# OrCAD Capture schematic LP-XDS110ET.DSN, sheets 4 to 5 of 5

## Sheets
4 4_EnergyTrace Power: size A3
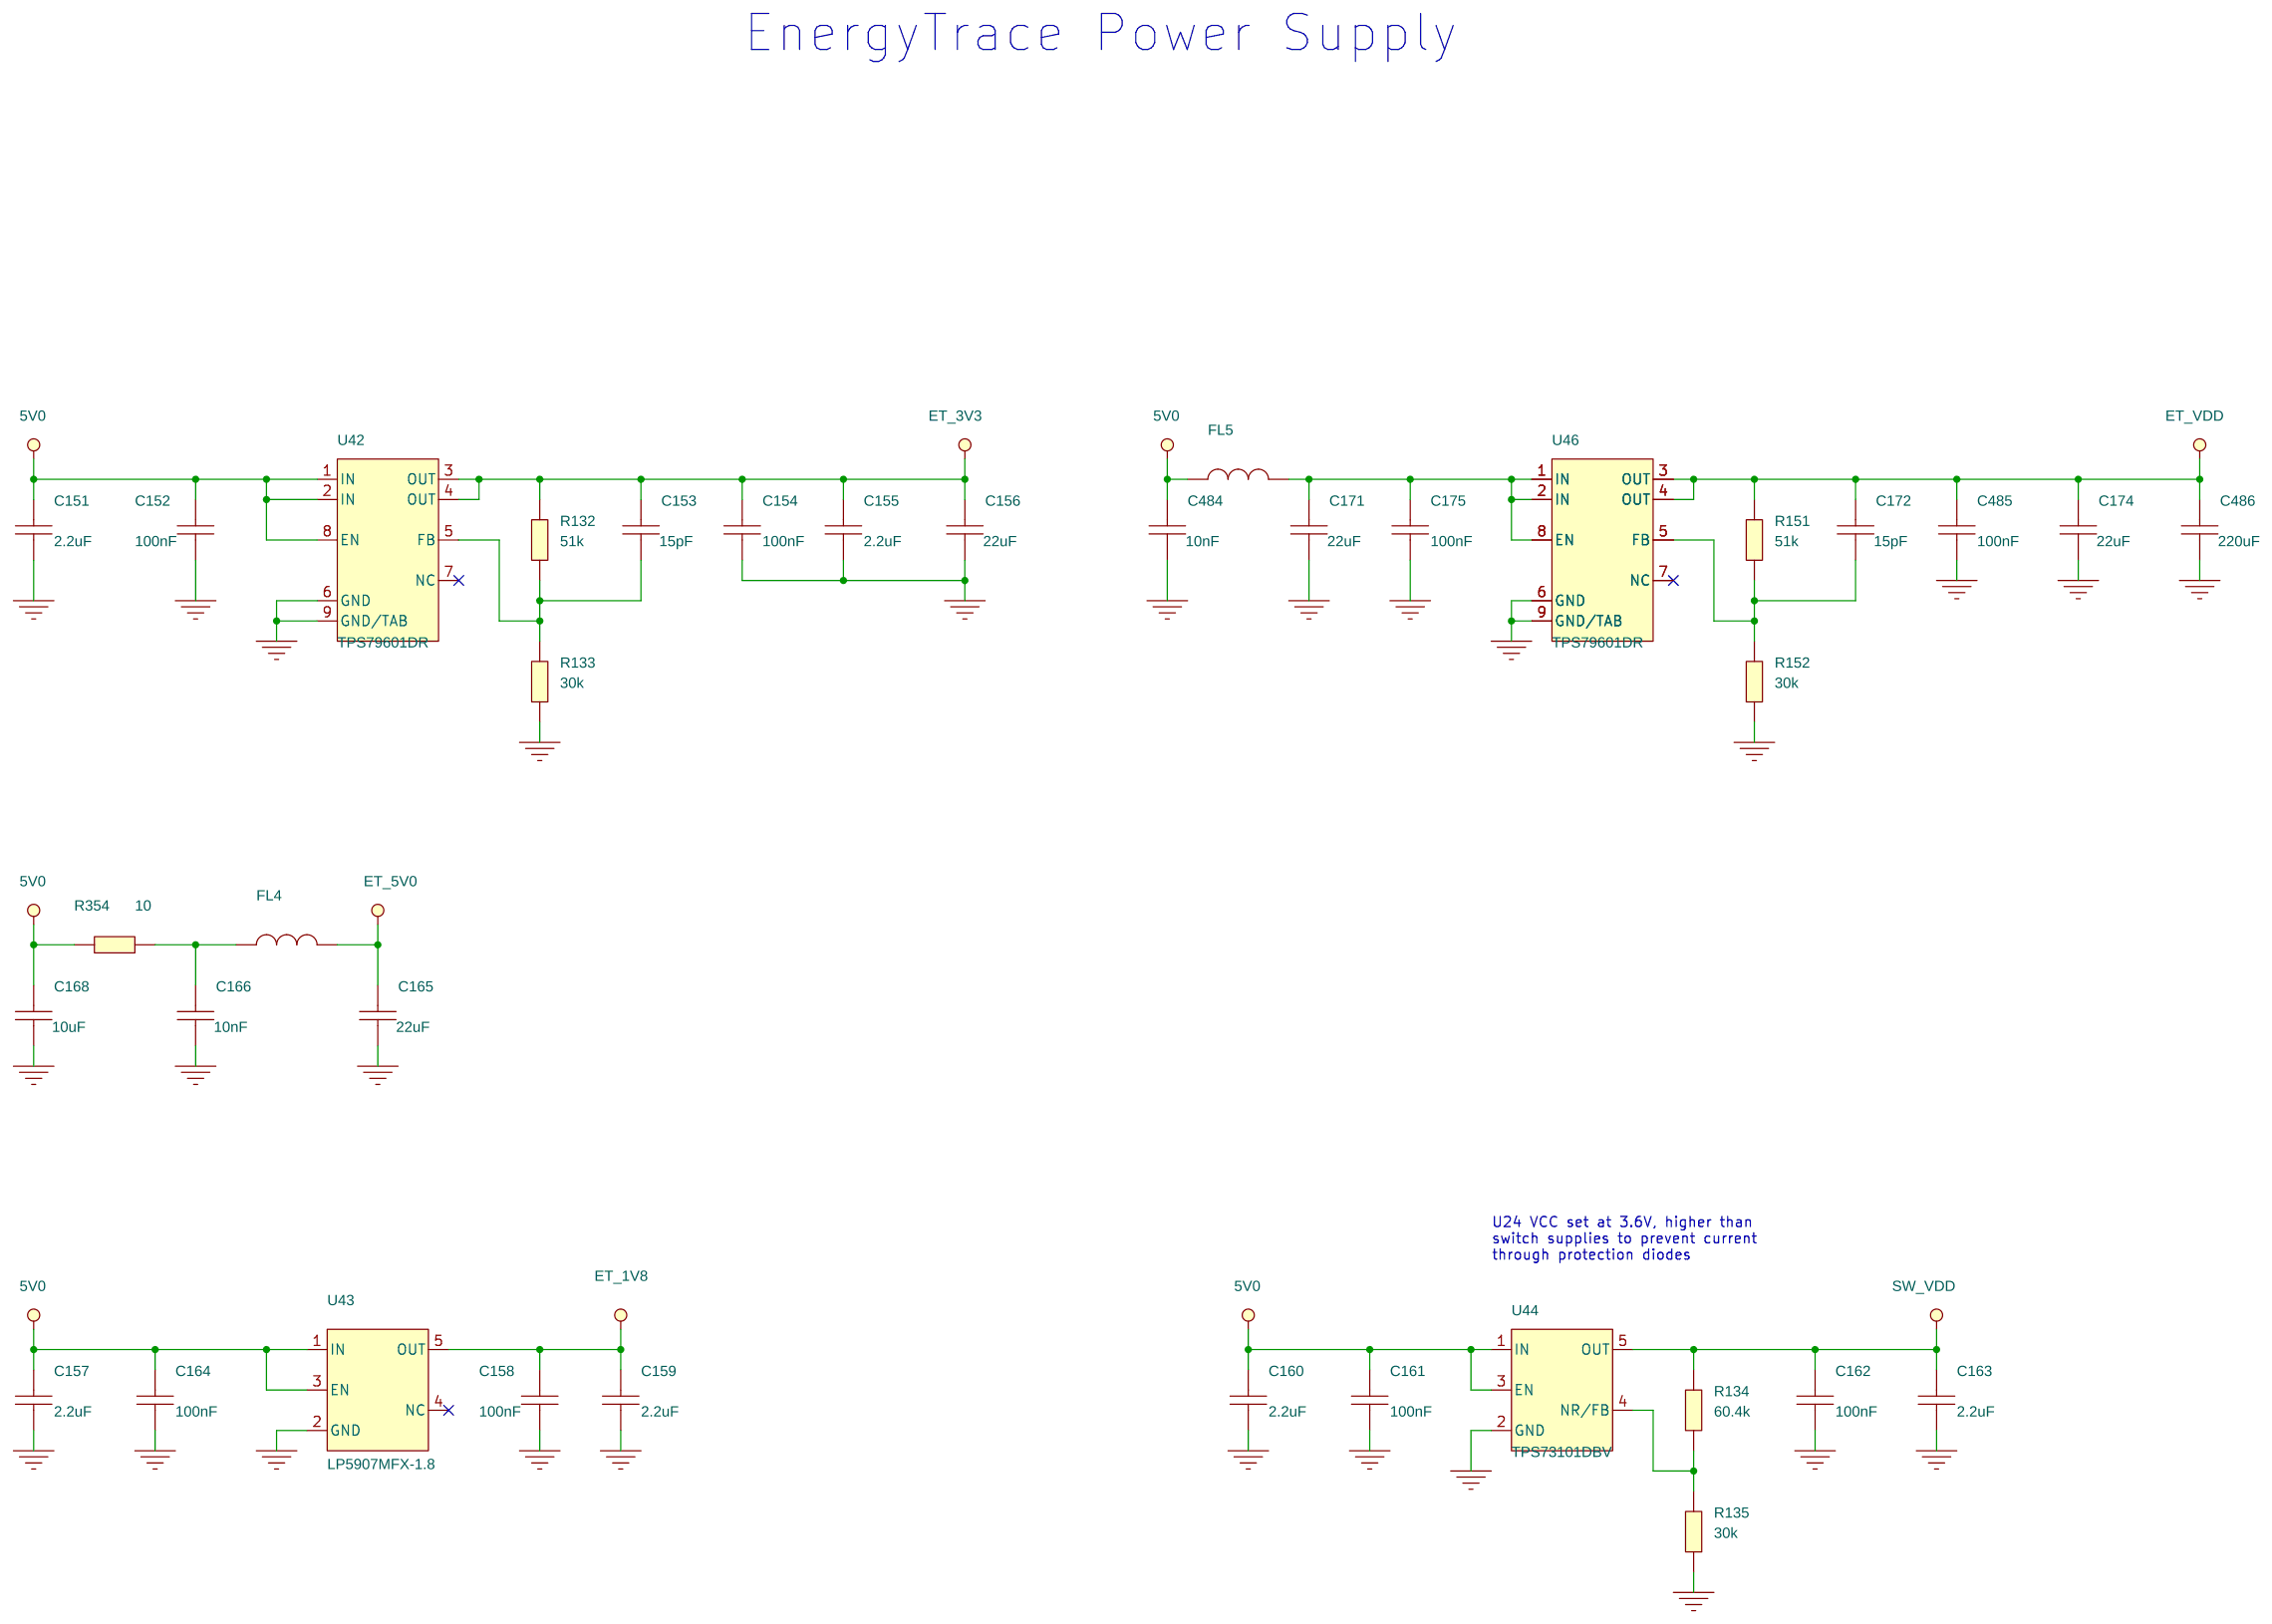
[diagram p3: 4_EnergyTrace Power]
5 5_Mech: size A3
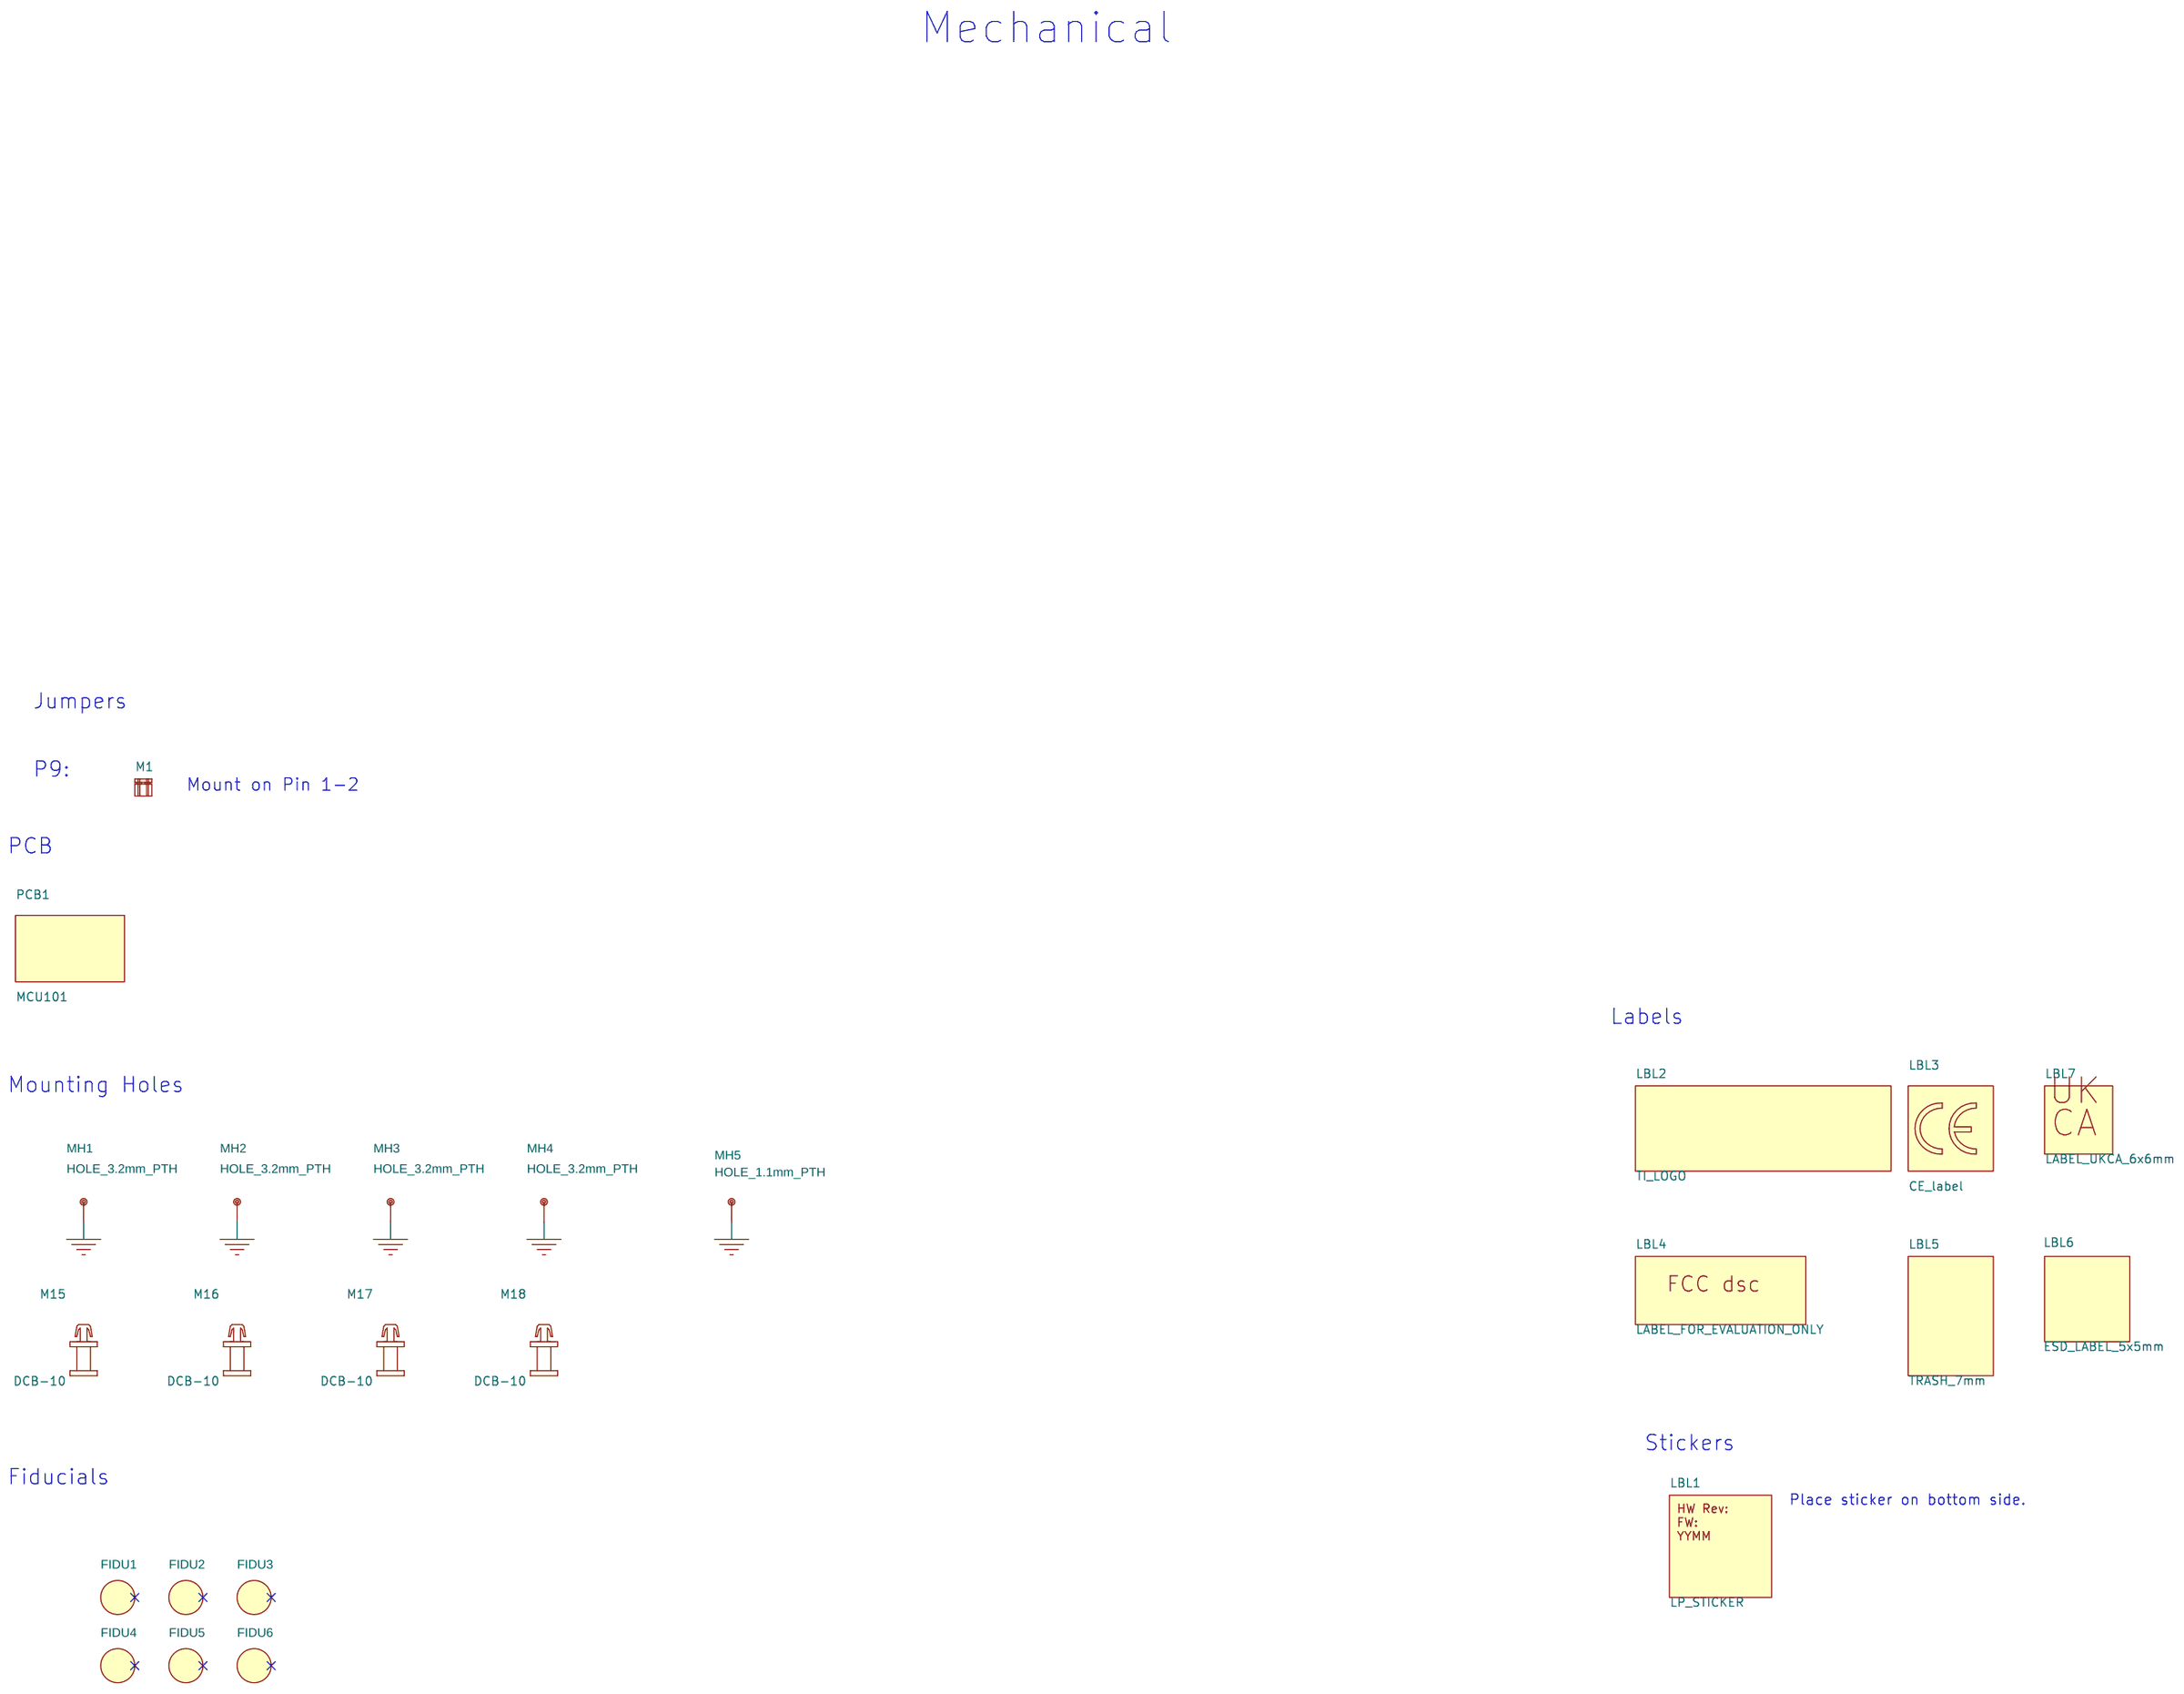
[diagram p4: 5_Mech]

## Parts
sheet 4_EnergyTrace Power
C151  2.2uF  [CAPC1005X60A2N]
C152  100nF  [CAPC0603X35B2N]
C153  15pF  [CAPC1005X60B2N]
C154  100nF  [CAPC0603X35B2N]
C155  2.2uF  [CAPC1005X60A2N]
C156  22uF  [CAPC1608X100A2N]
C157  2.2uF  [CAPC1005X60A2N]
C158  100nF  [CAPC0603X35B2N]
C159  2.2uF  [CAPC1005X60A2N]
C160  2.2uF  [CAPC1005X60A2N]
C161  100nF  [CAPC0603X35B2N]
C162  100nF  [CAPC0603X35B2N]
C163  2.2uF  [CAPC1005X60A2N]
C164  100nF  [CAPC0603X35B2N]
C165  22uF  [CAPC1608X100A2N]
C166  10nF  [CAPC1005X60B2N]
C168  10uF  [CAPC2012X150A2N]
C171  22uF  [CAPC1608X100A2N]
C172  15pF  [CAPC1005X60B2N]
C174  22uF  [CAPC1608X100A2N]
C175  100nF  [CAPC0603X35B2N]
C484  10nF  [CAPC1005X60B2N]
C485  100nF  [CAPC0603X35B2N]
C486  220uF  [CAPC3225X280A2N]
FL4  BLM18HE152SN1  [FIL_BLM18HE152SN1DN]
FL5  BLM18HE152SN1  [FIL_BLM18HE152SN1DN]
R132  51k  [RESC1005X40B2N]
R133  30k  [RESC1005X40B2N]
R134  60.4k  [RESC1005X40A2N]
R135  30k  [RESC1005X40B2N]
R151  51k  [RESC1005X40B2N]
R152  30k  [RESC1005X40B2N]
R354  10  [RESC1005X40A2N]
U42  TPS79601DR  [SON65P300X300X100-9AN]
U43  LP5907MFX-1.8  [SOT95P280X145-5A2N]
U44  TPS73101DBV  [SOT95P280X145-5A2N]
U46  TPS79601DR  [SON65P300X300X100-9AN]
sheet 5_Mech
FIDU1  FIDU_1.27mm  [FID127X142]
FIDU2  FIDU_1.27mm  [FID127X142]
FIDU3  FIDU_1.27mm  [FID127X142]
FIDU4  FIDU_1.27mm  [FID127X142]
FIDU5  FIDU_1.27mm  [FID127X142]
FIDU6  FIDU_1.27mm  [FID127X142]
LBL1  LP_STICKER
LBL2  TI_LOGO  [TI_LOGO_1]
LBL3  CE_label  [CE_MARKING]
LBL4  LABEL_FOR_EVALUATION_ONLY  [LABEL_FOR_EVALUATION_ONLY]
LBL5  TRASH_7mm  [TRASH_7MM]
LBL6  ESD_LABEL_5x5mm  [ESD_LABEL_5x5]
LBL7  LABEL_UKCA_6x6mm  [LABEL_UKCA_6MM]
M1  SNT-100-BK-G  [SAMTEC_SNT100BKG]
M15  DCB-10  [MECH_DCB10_A2B]
M16  DCB-10  [MECH_DCB10_A2B]
M17  DCB-10  [MECH_DCB10_A2B]
M18  DCB-10  [MECH_DCB10_A2B]
MH1  HOLE_3.2mm_PTH  [MTG320_380]
MH2  HOLE_3.2mm_PTH  [MTG320_380]
MH3  HOLE_3.2mm_PTH  [MTG320_380]
MH4  HOLE_3.2mm_PTH  [MTG320_380]
MH5  HOLE_1.1mm_PTH  [MTG110_170]
PCB1  MCU101  [TI_MCUxx]

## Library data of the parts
C151 C155 C157 C159 C160 C163 = CAPACITOR: CAPACITOR, CERAMIC X5R, 2.2uF, 25V, -10%/+10%, -55DEGC/+85DEGC, 0402, SMD; ALT_SYMBOLS: CAPC1005X60A2L,CAPC1005X60A2M; Additional Datasheet URL: http://search.murata.co.jp/Ceramy/image/img/w_hinm/L0005E.pdf; AutoDoc File: https://notefied-dynamic-precision.com/DB/Apps/Desktop/Item/Object.aspx?id=96297; BU Name: DYNAMIC PRECISION GDANSK; Budget Currency: EUR; Budget Price: 0.063; Budgetary Price: 0.063 EUR; Client Status: UNDER_REVIEW; Country of Origin: Missing Info; Datasheet URL: http://psearch.murata.com/capacitor/product/GRM155R61E225KE11%23.pdf; Datasheet URL 1: http://psearch.murata.com/capacitor/product/GRM155R61E225KE11%23.pdf; Datasheet URL 2: http://search.murata.co.jp/Ceramy/image/img/w_hinm/L0005E.pdf; Definied Quality: INDUSTRIAL; Dielectric Type: X5R; Esd Level: N/A; Lead Time: 19; LifeCycle Status: NRND; MPN: GRM155R60J225KE95D; MPN Status: NRND; MSL: 1; MTBF: N/A; MTBF Standard: N/A; Manufacturer: MURATA; Mass: 0.0031g; Max Oper Temp: +85DEGC; Max Tol: +10%; Maximum Operating Temperature: +85DEGC; Maximum Tolerance: +10%; Min Oper Temp: -55DEGC; Min Tol: -10%; Minimum Operating Temperature: -55DEGC; Minimum Tolerance: -10%; Mounting Type: SMD; NOTE Status: PREFERRED; NOTEfied URL: https://notefied-dynamic-precision.com/NOTEfiedWebInterface/part/show?partNumber=02-06058; Old Footprint: CAPC1005X60N; PCB Package: 0402; Packing Size: 10000; Packing Type: Tape & Reel; Part Number: 02-06058; Part Type: Capacitor|CERAMIC|0402|STANDARD; REACH/SVHC Compliance: Compliant; REACH/SVHC Details: SVHC List Version Jul 7, 2017; REACH/SVHC Source: REACH Declaration; REACH/SVHC Status: Unaffected; REACH/SVHC_COMPLIANCE: COMPLIANT; REACH/SVHC_DETAILS: SVHC List Version Jun 20, 2016; REACH/SVHC_SOURCE: REACH DECLARATION; REACH/SVHC_STATUS: UNAFFECTED; ROHS: Compliant; Rated Voltage: 25V; Revision: R007; RoHS Status: ROHS_COMPLIANT; Rtd Voltage: 25V; Status: Released; Texas Part Status: Under Review; Type: Capacitor; Vendor: MURATA; Vendor Part Number: GRM155R61E225KE11D; Vendor Part Status: Active; WEIGHT: 0.0031g
C152 C154 C158 C161 C162 C164 C175 C485 = CAPACITOR: CAPACITOR, CERAMIC X5R, 100nF, 10V, -10%/+10%, -55DEGC/+85DEGC, 0201, SMD; ALT_SYMBOLS: CAPC0603X35B2L,CAPC0603X35B2M; Additional Datasheet URL: http://psearch.en.murata.com/capacitor/product/GRM033R61A104KE84%23.html; AutoDoc File: https://notefied-dynamic-precision.com/DB/Apps/Desktop/Item/Object.aspx?id=96679; BU Name: DYNAMIC PRECISION GDANSK; Budget Currency: EUR; Budget Price: 0.008; Budgetary Price: 0.008 EUR; Client Status: UNDER_REVIEW; Country of Origin: Missing Info; Datasheet URL: http://psearch.murata.com/capacitor/product/GRM033R61A104KE84%23.pdf; Datasheet URL 1: http://psearch.murata.com/capacitor/product/GRM033R61A104KE84%23.pdf; Datasheet URL 2: http://search.murata.co.jp/Ceramy/image/img/w_hinm/L0005E.pdf; Dielectric Type: X5R; Lead Time: 17; LifeCycle Status: ACTIVE; MPN: GRM155R70J104KA01D; MPN Status: ACTIVE; Manufacturer: MURATA; Mass: 0.00033g; Max Oper Temp: +85DEGC; Max Tol: +10%; Maximum Operating Temperature: +85DEGC; Maximum Tolerance: +10%; Min Oper Temp: -55DEGC; Min Tol: -10%; Minimum Operating Temperature: -55DEGC; Minimum Tolerance: -10%; Mounting Type: SMD; NOTE Status: PREFERRED; NOTEfied URL: https://notefied-dynamic-precision.com/NOTEfiedWebInterface/part/show?partNumber=02-06085; Old Footprint: CAPC1005X60N,0402; PCB Package: 0201; Packing Size: 15000; Packing Type: Tape & Reel; Part Number: 02-06085; Part Type: Capacitor|CERAMIC|0201|STANDARD; REACH/SVHC Compliance: Compliant; REACH/SVHC Details: SVHC List Version Jul 7, 2017; REACH/SVHC Source: REACH Declaration; REACH/SVHC Status: Unaffected; REACH/SVHC_COMPLIANCE: COMPLIANT; REACH/SVHC_DETAILS: SVHC LIST VERSION Jun 20, 2016; REACH/SVHC_SOURCE: REACH DECLARATION; REACH/SVHC_STATUS: UNAFFECTED; ROHS: Compliant; Rated Voltage: 10V; Revision: R011; RoHS Status: ROHS_COMPLIANT; Rtd Voltage: 10V; Status: Released; Texas Part Status: Under Review; Type: Capacitor; Vendor: MURATA; Vendor Part Number: GRM033R61A104KE84D; Vendor Part Status: Active; WEIGHT: 0.00033g
C153 C172 = CAPACITOR: CAPACITOR, CERAMIC C0G/NP0, 15pF, 50V, -5%/+5%, -55DEGC/+125DEGC, 0402, SMD; Additional Datasheet URL: http://psearch.en.murata.com/capacitor/product/GRM1555C1H150JA01%23.html; AutoDoc File: https://notefied-dynamic-precision.com/DB/Apps/Desktop/Item/Object.aspx?id=114571; BU Name: TEXAS INSTRUMENTS NORWAY; Budget Currency: EUR; Budget Price: 0.006; Budgetary Price: 0.006 EUR; Client Status: UNDER_REVIEW; Country of Origin: Philippines; Datasheet URL: http://psearch.murata.com/capacitor/product/GRM1555C1H150JA01%23.pdf; Datasheet URL 1: http://psearch.murata.com/capacitor/product/GRM1555C1H150JA01%23.pdf; Datasheet URL 2: http://search.murata.co.jp/Ceramy/image/img/w_hinm/L0005E.pdf; Definied Quality: INDUSTRIAL; Dielectric Type: C0G/NP0; Esd Level: N/A; Exclusive for Customers: TEXAS INSTRUMENTS NORWAY; Lead Time: 12; LifeCycle Status: ACTIVE; MPN: CAPACITOR_0402_15pF_C0G/NP0_M_+/-5%_50V; MPN Status: ACTIVE; MSL: N/A; MTBF: N/A; MTBF Standard: N/A; Manufacturer: MANUFACTURER SELECTION; Mass: 0.0016g; Max Oper Temp: +125DEGC; Max Tol: +5%; Maximum Operating Temperature: +125DEGC; Maximum Tolerance: +5%; Min Oper Temp: -55DEGC; Min Tol: -5%; Minimum Operating Temperature: -55DEGC; Minimum Tolerance: -5%; Mounting Type: SMD; NOTE Status: PREFERRED; NOTEfied URL: https://notefied-dynamic-precision.com/NOTEfiedWebInterface/part/show?partNumber=02-07776; Notes: Standard item: Duplicate Reason: custom footprint for TEXAS INSTRUMENTS NORWAY.; Old Footprint: CAPC1005X60N; PCB Package: 0402; Packing Size: 10000; Packing Type: Tape & Reel; Part Number: 02-07776; Part Type: Capacitor|CERAMIC|0402|STANDARD; REACH/SVHC Compliance: Compliant; REACH/SVHC Details: SVHC List Version Jul 7, 2017; REACH/SVHC Source: REACH Declaration; REACH/SVHC Status: Unaffected; REACH/SVHC_COMPLIANCE: COMPLIANT; REACH/SVHC_DETAILS: SVHC LIST VERSION Dec 17, 2015; REACH/SVHC_SOURCE: REACH DECLARATION; REACH/SVHC_STATUS: UNAFFECTED; ROHS: Compliant; Rated Voltage: 50V; Revision: R009; RoHS Status: ROHS_COMPLIANT; Rtd Voltage: 50V; Status: Released; Texas Part Status: Under Review; Type: Capacitor; Vendor: MURATA; Vendor Part Number: GRM1555C1H150JA01D; Vendor Part Status: Active; WEIGHT: 0.0016g
C156 C165 C174 = CAPACITOR: CAPACITOR, CERAMIC, X5R, 22uF, 6.3V, -20%/+20%, -55DEGC/+85DEGC, 0603, SMD; ALT_SYMBOLS: CAPC1608X100A2L,CAPC1608X100A2M; Additional Datasheet URL: http://psearch.en.murata.com/capacitor/product/GRM188R60J226MEA0%23.html; AutoDoc File: https://notefied-dynamic-precision.com/DB/Apps/Desktop/Item/Object.aspx?id=104385; BU Name: DYNAMIC PRECISION GDANSK; Budget Currency: EUR; Budget Price: 0.062; Budgetary Price: 0.062 EUR; Client Status: UNDER_REVIEW; Country of Origin: Japan; Datasheet URL: http://psearch.murata.com/capacitor/product/GRM188R60J226MEA0%23.pdf; Datasheet URL 1: http://psearch.murata.com/capacitor/product/GRM188R60J226MEA0%23.pdf; Datasheet URL 2: http://search.murata.co.jp/Ceramy/image/img/w_hinm/L0005E.pdf; Dielectric Type: X5R; Lead Time: 26; Mass: 0.0091g; Max Oper Temp: +85DEGC; Max Tol: +20%; Maximum Operating Temperature: +85DEGC; Maximum Tolerance: +20%; Min Oper Temp: -55DEGC; Min Tol: -20%; Minimum Operating Temperature: -55DEGC; Minimum Tolerance: -20%; Mounting Type: SMD; NOTEfied URL: https://notefied-dynamic-precision.com/NOTEfiedWebInterface/part/show?partNumber=02-07053; PCB Package: 0603; Packing Size: 4000; Packing Type: Tape & Reel; Part Number: 02-07053; Part Type: Capacitor|CERAMIC|0603|STANDARD; REACH/SVHC Compliance: Compliant; REACH/SVHC Details: SVHC List Version Jul 7, 2017; REACH/SVHC Source: REACH Declaration; REACH/SVHC Status: Unaffected; REACH/SVHC_COMPLIANCE: COMPLIANT; REACH/SVHC_DETAILS: SVHC LIST VERSION Dec 17, 2015; REACH/SVHC_SOURCE: REACH DECLARATION; REACH/SVHC_STATUS: UNAFFECTED; ROHS: Compliant; Rated Voltage: 6.3V; Revision: R008; RoHS Status: ROHS_COMPLIANT; Rtd Voltage: 6.3V; Status: Released; Texas Part Status: Under Review; Type: Capacitor; Vendor: MURATA; Vendor Part Number: GRM188R60J226MEA0D; Vendor Part Status: Active; Weight: 0.0091g
C166 C484 = CAPACITOR: CAPACITOR, CERAMIC X7R, 10nF, 25V, -10%/+10%, -55DEGC/+125DEGC, 0402, SMD; Additional Datasheet URL: http://psearch.en.murata.com/capacitor/product/GRM155R71E103KA01%23.html; AutoDoc File: https://notefied-dynamic-precision.com/DB/Apps/Desktop/Item/Object.aspx?id=114570; BU Name: TEXAS INSTRUMENTS NORWAY; Budget Currency: EUR; Budget Price: 0.003; Budgetary Price: 0.003 EUR; Client Status: UNDER_REVIEW; Country of Origin: China; Datasheet URL: http://psearch.murata.com/capacitor/product/GRM155R71E103KA01%23.pdf; Datasheet URL 1: http://psearch.murata.com/capacitor/product/GRM155R71E103KA01%23.pdf; Datasheet URL 2: http://search.murata.co.jp/Ceramy/image/img/w_hinm/L0005E.pdf; Definied Quality: INDUSTRIAL; Dielectric Type: X7R; Esd Level: N/A; Exclusive for Customers: TEXAS INSTRUMENTS NORWAY; Lead Time: 18; LifeCycle Status: ACTIVE; MPN: CAPACITOR_0402_10nF_X7R_M_+/-10%_25V; MPN Status: ACTIVE; MSL: N/A; MTBF: N/A; MTBF Standard: N/A; Manufacturer: MANUFACTURER SELECTION; Mass: 0.0016g; Max Oper Temp: +125DEGC; Max Tol: +10%; Maximum Operating Temperature: +125DEGC; Maximum Tolerance: +10%; Min Oper Temp: -55DEGC; Min Tol: -10%; Minimum Operating Temperature: -55DEGC; Minimum Tolerance: -10%; Mounting Type: SMD; NOTE Status: PREFERRED; NOTEfied URL: https://notefied-dynamic-precision.com/NOTEfiedWebInterface/part/show?partNumber=02-07775; Notes: Standard item: Duplicate Reason: custom footprint for TEXAS INSTRUMENTS NORWAY.; Old Footprint: CAPC1005X60N; PCB Package: 0402; Packing Size: 10000; Packing Type: Tape & Reel; Part Number: 02-07775; Part Type: Capacitor|CERAMIC|0402|STANDARD; REACH/SVHC Compliance: Compliant; REACH/SVHC Details: SVHC List Version Jul 7, 2017; REACH/SVHC Source: REACH Declaration; REACH/SVHC Status: Unaffected; REACH/SVHC_COMPLIANCE: COMPLIANT; REACH/SVHC_DETAILS: SVHC LIST VERSION Dec 17, 2015; REACH/SVHC_SOURCE: MATERIAL DECLARATION; REACH/SVHC_STATUS: UNAFFECTED; ROHS: Compliant; Rated Voltage: 25V; Revision: R013; RoHS Status: ROHS_COMPLIANT; Rtd Voltage: 25V; Status: Released; Texas Part Status: Under Review; Type: Capacitor; Vendor: MURATA; Vendor Part Number: GRM155R71E103KA01D; Vendor Part Status: Active; WEIGHT: 0.0016g
C168 = CAPACITOR: CAPACITOR, CERAMIC X7R, 10uF, 16V, -10%/+10%, -55DEGC/+125DEGC, 0805, SMD; ALT_SYMBOLS: CAPC2012X150A2L,CAPC2012X150A2M; Additional Datasheet URL: http://www.samsungsem.com/kr/support/product-search/mlcc/__icsFiles/afieldfile/2016/08/18/S_CL21B106KOQNNNE.pdf; AutoDoc File: https://notefied-dynamic-precision.com/DB/Apps/Desktop/Item/Object.aspx?id=94511; BU Name: DYNAMIC PRECISION GDANSK; Budget Currency: USD; Budget Price: 0.05; Budgetary Price: 0.05 USD; Client Status: UNDER_REVIEW; Country of Origin: South Korea; Datasheet URL: http://www.samsungsem.com/kr/support/library/product-catalog/__icsFiles/afieldfile/2016/09/27/MLCC.pdf; Datasheet URL 1: http://www.samsungsem.com/kr/front/downloadcms.do?path=/kr/support/product-search/mlcc/__icsFiles/afieldfile/2015/10/15&fileName=S_CL21B106KOQNNNE.pdf; Datasheet URL 2: N/A; Dielectric Type: X7R; Lead Time: 11; Mass: 0.0166g; Max Oper Temp: +125DEGC; Max Tol: +10%; Maximum Operating Temperature: +125DEGC; Maximum Tolerance: +10%; Min Oper Temp: -55DEGC; Min Tol: -10%; Minimum Operating Temperature: -55DEGC; Minimum Tolerance: -10%; Mounting Type: SMD; NOTEfied URL: https://notefied-dynamic-precision.com/NOTEfiedWebInterface/part/show?partNumber=02-05775; PCB Package: 0805; Packing Size: 2000; Packing Type: Tape & Reel; Part Number: 02-05775; Part Type: Capacitor|CERAMIC|0805|STANDARD; REACH/SVHC Compliance: Compliant; REACH/SVHC Details: SVHC List Version Jan 12, 2017; REACH/SVHC Source: REACH Declaration; REACH/SVHC Status: Unaffected; ROHS: Compliant; Rated Voltage: 16V; Revision: R007; RoHS Status: ROHS_COMPLIANT; Rtd Voltage: 16V; Status: Released; Texas Part Status: Under Review; Type: Capacitor; Vendor: SAMSUNG ELECTRO-MECHANICS; Vendor Part Number: CL21B106KOQNNNE; Vendor Part Status: Active; Weight: 0.0166g
C171 = CAPACITOR: CAPACITOR, CERAMIC, X5R, 22uF, 6.3V, -20%/+20%, -55DEGC/+85DEGC, 0603, SMD; ALT_SYMBOLS: CAPC1608X100A2L,CAPC1608X100A2M; Additional Datasheet URL: http://psearch.en.murata.com/capacitor/product/GRM188R60J226MEA0%23.html; AutoDoc File: https://notefied-dynamic-precision.com/DB/Apps/Desktop/Item/Object.aspx?id=96297; BU Name: DYNAMIC PRECISION GDANSK; Budget Currency: EUR; Budget Price: 0.063; Budgetary Price: 0.062 EUR; Client Status: UNDER_REVIEW; Country of Origin: Japan; Datasheet URL: https://search.murata.co.jp/Ceramy/image/img/A01X/G101/ENG/GRM188R60J226MEA0-01A.pdf; Datasheet URL 1: http://psearch.murata.com/capacitor/product/GRM155R61E225KE11%23.pdf; Datasheet URL 2: http://search.murata.co.jp/Ceramy/image/img/w_hinm/L0005E.pdf; Definied Quality: INDUSTRIAL; Dielectric Type: X5R; Esd Level: N/A; Lead Time: 26; LifeCycle Status: NRND; MPN: GRM155R60J225KE95D; MPN Status: NRND; MSL: 1; MTBF: N/A; MTBF Standard: N/A; Manufacturer: MURATA; Mass: 0.0091g; Max Oper Temp: +85DEGC; Max Tol: +10%; Maximum Operating Temperature: +85DEGC; Maximum Tolerance: +20%; Min Oper Temp: -55DEGC; Min Tol: -10%; Minimum Operating Temperature: -55DEGC; Minimum Tolerance: -20%; Mounting Type: SMD; NOTE Status: PREFERRED; NOTEfied URL: https://notefied-dynamic-precision.com/NOTEfiedWebInterface/part/show?partNumber=02-07053; Old Footprint: CAPC1005X60N; PCB Package: 0603; Packing Size: 4000; Packing Type: Tape & Reel; Part Number: 02-07053; Part Type: Capacitor|CERAMIC|0603|STANDARD; REACH/SVHC Compliance: Compliant; REACH/SVHC Details: SVHC List Version Jul 7, 2017; REACH/SVHC Source: REACH Declaration; REACH/SVHC Status: Unaffected; REACH/SVHC_COMPLIANCE: COMPLIANT; REACH/SVHC_DETAILS: SVHC List Version Jun 20, 2016; REACH/SVHC_SOURCE: REACH DECLARATION; REACH/SVHC_STATUS: UNAFFECTED; ROHS: Compliant; Rated Voltage: 6.3V; Revision: R010; RoHS Status: ROHS_COMPLIANT; Rtd Voltage: 25V; Status: Released; Texas Part Status: Under Review; Type: Capacitor; Vendor: MURATA; Vendor Part Number: GRM188R60J226MEA0D; Vendor Part Status: Active; WEIGHT: 0.0031g
C486 = CAPACITOR: CAPACITOR, CERAMIC X5R, 220uF, 6.3V, -20%/+20%, -55DEGC/+85DEGC, 1210, SMD; ALT_SYMBOLS: CAPC3225X280A2L,CAPC3225X280A2M; Additional Datasheet URL: N/A; Budgetary Price: 1.1389 EUR; Country of Origin: Philippines; Datasheet URL: https://search.murata.co.jp/Ceramy/image/img/A01X/G101/ENG/GRM32ER60J227ME05-01A.pdf; Dielectric Type: X5R; Mass: 0.11g; Maximum Operating Temperature: +85DEGC; Maximum Tolerance: +20%; Minimum Operating Temperature: -55DEGC; Minimum Tolerance: -20%; Mounting Type: SMD; NOTEfied URL: https://notefied-dynamic-precision.com/NOTEfiedWebInterface/part/show?partNumber=02-08923; PCB Package: 1210; Packing Size: 1000; Packing Type: Tape & Reel; Part Number: 02-08923; Part Type: Capacitor|CERAMIC|1210|STANDARD; REACH/SVHC Compliance: Compliant; REACH/SVHC Details: SVHC List Version Jan 15, 2018; REACH/SVHC Source: REACH Declaration; REACH/SVHC Status: Unaffected; ROHS: Compliant; Rated Voltage: 6.3V; Revision: R001; Status: Released; Texas Part Status: Under Review; Type: Capacitor; Vendor: MURATA; Vendor Part Number: GRM32ER60J227ME05L; Vendor Part Status: Active
FL4 FL5 = FILTER_2PIN: FILTER, EMI, FERRITE BEAD, 1500@100MHz, -25%/+25%, -55DEGC/+125DEGC, 0603, SMD; ALT_SYMBOLS: FIL_BLM18HE152SN1DL,FIL_BLM18HE152SN1DM; Additional Datasheet URL: http://www.murata.com/en-global/products/productdetail.aspx?cate=luNoiseSupprFilteChipFerriBead&partno=BLM18HE152SN1%23; AutoDoc File: http://notefied-dynamic-precision.com/DB/Apps/Desktop/Item/Object.aspx?id=85575; Budget Currency: EUR; Budget Price: 0.085; Budgetary Price: 0.065 EUR; CLASS: IC; Country of Origin: Japan,Singapore,Thailand; Datasheet URL: http://www.murata.com/en-global/api/pdfdownloadapi?cate=luNoiseSupprFilteChipFerriBead&partno=BLM18HE152SN1%23; Datasheet URL 1: http://search.murata.co.jp/Ceramy/image/img/PDF/ENG/L0110S0101BLM18H.pdf; Datasheet URL 2: http://search.murata.co.jp/Ceramy/image/img/PDF/ENG/L0110S0101BLM18H.pdf; FPLIST: FIL_BLM18HE152SN1DN,FIL_BLM18HE152SN1DL,FIL_BLM18HE152SN1DM; Frequency: 100MHz; Impedance: 1500; Inductance: N/A; Lead Time: 9; MPN: BLM18HE152SN1D; MPN Status: ACTIVE; Manufacturer: MURATA; Mass: 0.006g; Max Oper Temp: +125DEGC; Max Tol: +25%; Maximum Operating Temperature: +125DEGC; Maximum Tolerance: +25%; Min Oper Temp: -55DEGC; Min Tol: -25%; Minimum Operating Temperature: -55DEGC; Minimum Tolerance: -25%; Mounting Type: SMD; NOTE Status: PREFERRED; NOTEfied URL: https://notefied-dynamic-precision.com/NOTEfiedWebInterface/part/show?partNumber=04-00470; PCB Package: 0603; Packing Size: 4000; Packing Type: Tape & Reel; Part Number: 04-00470; Part Type: Filter|EMI|FERRITE BEAD|0603; REACH/SVHC Compliance: Compliant; REACH/SVHC Details: SVHC List Version Jul 7, 2017; REACH/SVHC Source: REACH Declaration; REACH/SVHC Status: Unaffected; ROHS: Compliant; Rated Current: 0.5A; Rated Voltage: N/A; Revision: R009; RoHS Status: ROHS_COMPLIANT; Rtd Current: 0.5A; Status: Released; Texas Part Status: Under Review; Type: Filter; Vendor: MURATA; Vendor Part Number: BLM18HE152SN1D; Vendor Part Status: Active; WEIGHT: 0.006g
R132 R151 = RESISTOR: RESISTOR, THICK FILM, 51k, -5%/+5%, 0.063W, 50V, -55DEGC/+155DEGC, 0402, SMD; Additional Datasheet URL: N/A; AutoDoc File: https://notefied-dynamic-precision.com/DB/Apps/Desktop/Item/Object.aspx?id=114564; BU Name: TEXAS INSTRUMENTS NORWAY; Budget Currency: EUR; Budget Price: 0.014; Budgetary Price: 0.014 EUR; Client Status: UNDER_REVIEW; Country of Origin: Israel; Datasheet URL: http://www.vishay.com/docs/20035/dcrcwe3.pdf; Datasheet URL 1: http://www.vishay.com/docs/20035/dcrcwe3.pdf; Datasheet URL 2: N/A; Definied Quality: INDUSTRIAL; Esd Level: N/A; Exclusive for Customers: TEXAS INSTRUMENTS NORWAY; Lead Time: 18; LifeCycle Status: ACTIVE; MPN: RESISTOR_0402_51k_+/-5%_50V_0.063W_M_+/-200ppm; MPN Status: ACTIVE; MSL: N/A; MTBF: N/A; MTBF Standard: N/A; Manufacturer: MANUFACTURER SELECTION; Mass: 0.00065g; Max Oper Temp: +155DEGC; Max TC: +200PPM/DEGC; Max Tol: +5%; Maximum Operating Temperature: +155DEGC; Maximum Temperature Coefficient: +200PPM/DEGC; Maximum Tolerance: +5%; Min Oper Temp: -55DEGC; Min TC: -200PPM/DEGC; Min Tol: -5%; Minimum Operating Temperature: -55DEGC; Minimum Temperature Coeficient: -200PPM/DEGC; Minimum Tolerance: -5%; Mounting Type: SMD; NOTE Status: PREFERRED; NOTEfied URL: https://notefied-dynamic-precision.com/NOTEfiedWebInterface/part/show?partNumber=01-22491; Notes: Standard item: Duplicate Reason: custom footprint for TEXAS INSTRUMENTS NORWAY.; Old Footprint: RESC1005X40N; PCB Package: 0402; Packing Size: 10000; Packing Type: Tape & Reel; Part Number: 01-22491; Part Type: Resistor|0402|STANDARD; REACH/SVHC Compliance: Compliant; REACH/SVHC Details: SVHC List Version Jun 20, 2016; REACH/SVHC Source: Material Declaration; REACH/SVHC Status: Unaffected; REACH/SVHC_COMPLIANCE: COMPLIANT; REACH/SVHC_DETAILS: SVHC LIST VERSION Jun 20, 2016; REACH/SVHC_SOURCE: MATERIAL DECLARATION; REACH/SVHC_STATUS: UNAFFECTED; ROHS: Exempt; Rated Current: N/A; Rated Power: 0.063W; Rated Voltage: 50V; Resistor Type: THICK FILM; Revision: R007; RoHS Status: ROHS_COMPLIANT; Rtd Current: N/A; Rtd Power: 0.063W; Rtd Voltage: 50V; Status: Released; Texas Part Status: Under Review; Type: Resistor; Vendor: VISHAY; Vendor Part Number: CRCW040251K0JNED; Vendor Part Status: Active; WEIGHT: 0.00065g
R133 R135 R152 = RESISTOR: RESISTOR, THICK FILM, 30k, -5%/+5%, 0.063W, 50V, -55DEGC/+155DEGC, 0402, SMD; Additional Datasheet URL: N/A; AutoDoc File: https://notefied-dynamic-precision.com/DB/Apps/Desktop/Item/Object.aspx?id=114563; BU Name: TEXAS INSTRUMENTS NORWAY; Budget Currency: EUR; Budget Price: 0.014; Budgetary Price: 0.014 EUR; Client Status: UNDER_REVIEW; Country of Origin: Missing Info; Datasheet URL: http://www.vishay.com/docs/20035/dcrcwe3.pdf; Datasheet URL 1: http://www.vishay.com/docs/20035/dcrcwe3.pdf; Datasheet URL 2: N/A; Definied Quality: INDUSTRIAL; Esd Level: N/A; Exclusive for Customers: TEXAS INSTRUMENTS NORWAY; Lead Time: 18; LifeCycle Status: ACTIVE; MPN: RESISTOR_0402_30k_+/-5%_50V_0.063W_M_+/-200ppm; MPN Status: ACTIVE; MSL: N/A; MTBF: N/A; MTBF Standard: N/A; Manufacturer: MANUFACTURER SELECTION; Mass: 0.00065g; Max Oper Temp: +155DEGC; Max TC: +200PPM/DEGC; Max Tol: +5%; Maximum Operating Temperature: +155DEGC; Maximum Temperature Coefficient: +200PPM/DEGC; Maximum Tolerance: +5%; Min Oper Temp: -55DEGC; Min TC: -200PPM/DEGC; Min Tol: -5%; Minimum Operating Temperature: -55DEGC; Minimum Temperature Coeficient: -200PPM/DEGC; Minimum Tolerance: -5%; Mounting Type: SMD; NOTE Status: PREFERRED; NOTEfied URL: https://notefied-dynamic-precision.com/NOTEfiedWebInterface/part/show?partNumber=01-22490; Notes: Standard item: Duplicate Reason: custom footprint for TEXAS INSTRUMENTS NORWAY.; Old Footprint: RESC1005X40N; PCB Package: 0402; Packing Size: 10000; Packing Type: Tape & Reel; Part Number: 01-22490; Part Type: Resistor|0402|STANDARD; REACH/SVHC Compliance: Compliant; REACH/SVHC Details: SVHC List Version Jun 20, 2016; REACH/SVHC Source: Material Declaration; REACH/SVHC Status: Unaffected; REACH/SVHC_COMPLIANCE: COMPLIANT; REACH/SVHC_DETAILS: SVHC LIST VERSION Jun 20, 2016; REACH/SVHC_SOURCE: MATERIAL DECLARATION; REACH/SVHC_STATUS: UNAFFECTED; ROHS: Exempt; Rated Current: N/A; Rated Power: 0.063W; Rated Voltage: 50V; Resistor Type: THICK FILM; Revision: R007; RoHS Status: ROHS_COMPLIANT; Rtd Current: N/A; Rtd Power: 0.063W; Rtd Voltage: 50V; Status: Released; Texas Part Status: Under Review; Type: Resistor; Vendor: VISHAY; Vendor Part Number: CRCW040230K0JNED; Vendor Part Status: Active; WEIGHT: 0.00065g
R134 = RESISTOR: RESISTOR, THICK FILM, 60.4k, -1%/+1%, 0.063W, 50V, -55DEGC/+155DEGC, 0402, SMD; ALT_SYMBOLS: RESC1005X40A2L,RESC1005X40A2M; Additional Datasheet URL: N/A; AutoDoc File: https://notefied-dynamic-precision.com/DB/Apps/Desktop/Item/Object.aspx?id=59465; BU Name: DYNAMIC PRECISION GDANSK; Budget Currency: EUR; Budget Price: 0.012; Budgetary Price: 0.012 EUR; Client Status: UNDER_REVIEW; Country of Origin: Israel; Datasheet URL: http://www.vishay.com/docs/20035/dcrcwe3.pdf; Datasheet URL 1: http://www.vishay.com/docs/20035/dcrcwe3.pdf; Datasheet URL 2: N/A; Lead Time: 14; Mass: 0.00060916g; Max Oper Temp: +155DEGC; Max TC: +100PPM/DEGC; Max Tol: +1%; Maximum Operating Temperature: +155DEGC; Maximum Temperature Coefficient: +100PPM/DEGC; Maximum Tolerance: +1%; Min Oper Temp: -55DEGC; Min TC: -100PPM/DEGC; Min Tol: -1%; Minimum Operating Temperature: -55DEGC; Minimum Temperature Coeficient: -100PPM/DEGC; Minimum Tolerance: -1%; Mounting Type: SMD; NOTEfied URL: https://notefied-dynamic-precision.com/NOTEfiedWebInterface/part/show?partNumber=01-04658; PCB Package: 0402; Packing Size: 10000; Packing Type: Tape & Reel; Part Number: 01-04658; Part Type: Resistor|0402|PRECISION; REACH/SVHC Compliance: Compliant; REACH/SVHC Details: SVHC List Version Jun 20, 2016; REACH/SVHC Source: Material Declaration; REACH/SVHC Status: Unaffected; ROHS: Exempt; Rated Current: N/A; Rated Power: 0.063W; Rated Voltage: 50V; Resistor Type: THICK FILM; Revision: R012; RoHS Status: ROHS_COMPLIANT_WITH_EXEMPTION; Rtd Current: N/A; Rtd Power: 0.063W; Rtd Voltage: 50V; Status: Released; Texas Part Status: Under Review; Type: Resistor; Vendor: VISHAY; Vendor Part Number: CRCW040260K4FKED; Vendor Part Status: Active; Weight: 0.00060916g
R354 = RESISTOR: RESISTOR, THICK FILM, 10, -1%/+1%, 0.063W, 50V, -55DEGC/+155DEGC, 0402, SMD; ALT_SYMBOLS: RESC1005X40A2L,RESC1005X40A2M; Additional Datasheet URL: N/A; Budgetary Price: 0.012 EUR; Country of Origin: Israel; Datasheet URL: http://www.vishay.com/docs/20035/dcrcwe3.pdf; FPLIST: RESC1005X40A2N,RESC1005X40C2N; Lead Time: 14; Mass: 0.00060916g; Maximum Operating Temperature: +155DEGC; Maximum Temperature Coefficient: +100PPM/DEGC; Maximum Tolerance: +1%; Minimum Operating Temperature: -55DEGC; Minimum Temperature Coeficient: -100PPM/DEGC; Minimum Tolerance: -1%; Mounting Type: SMD; NOTEfied URL: https://notefied-dynamic-precision.com/NOTEfiedWebInterface/part/show?partNumber=01-00234; PCB Package: 0402; Packing Size: 10000; Packing Type: Tape & Reel; Part Number: 01-00234; Part Type: Resistor|0402|PRECISION; REACH/SVHC Compliance: Compliant; REACH/SVHC Details: SVHC List Version Jul 07, 2017; REACH/SVHC Source: REACH Declaration; REACH/SVHC Status: Unaffected; ROHS: Exempt; Rated Current: N/A; Rated Power: 0.063W; Rated Voltage: 50V; Resistor Type: THICK FILM; Revision: R012; Status: Released; Texas Part Status: Under Review; Type: Resistor; Vendor: VISHAY; Vendor Part Number: CRCW040210R0FKED; Vendor Part Status: Active
U42 U46 = IC_PM_TPS79601_SON8: IC, ANALOG, ULTRALOW-NOISE, HIGH PSRR, FAST, RF, 1A LOW-DROPOUT LINEAR REGULATORS, VIN:2.7V TO 5.5V, VOUT:1.2V TO 5.5V, SON8, SMD; ALT_SYMBOLS: SON65P300X300X100-9AL,SON65P300X300X100-9AM; Additional Datasheet URL: http://www.ti.com/litv/pdf/mpds118j; AutoDoc File: http://notefied-dynamic-precision.com/DB/Apps/Desktop/Item/Object.aspx?id=96546; Budget Currency: USD; Budget Price: 1; Budgetary Price: 1 USD; Country of Origin: Malaysia; Datasheet URL: http://www.ti.com/lit/ds/symlink/tps796.pdf; Datasheet URL 1: http://www.ti.com/litv/pdf/mpds118j; Datasheet URL 2: http://www.ti.com/lit/ds/symlink/tps79601.pdf; FPLIST: SON65P300X300X100-9AN,SON65P300X300X100-9AL,SON65P300X300X100-9AM; Lead Time: 6; LifeCycle Status: ACTIVE; MPN: TPS79601DRBR; MPN Status: ACTIVE; MSL: 2; Manufacturer: TEXAS INSTRUMENTS; Mass: 0.0247g; Max Oper Temp: +125DEGC; Maximum Operating Temperature: +125DEGC; Min Oper Temp: -40DEGC; Minimum Operating Temperature: -40DEGC; Mounting Type: SMD; NOTE Status: PREFERRED; NOTEfied URL: https://notefied-dynamic-precision.com/NOTEfiedWebInterface/part/show?partNumber=18-29530; PCB Package: SON8; Packing Size: 3000; Packing Type: Tape & Reel; Part Number: 18-29530; Part Type: IC|ANALOG|PM|REGULATOR; REACH/SVHC Compliance: Compliant; REACH/SVHC Details: SVHC List Version Jun 20, 2016; REACH/SVHC Source: Material Declaration; REACH/SVHC Status: Unaffected; ROHS: Compliant; Rated Voltage: 1.2V TO 5.4V; Revision: R006; RoHS Status: ROHS_COMPLIANT; Rtd Voltage: 1.2V TO 5.4V; Status: Released; Texas Part Status: Under Review; Type: IC; Vendor: TEXAS INSTRUMENTS; Vendor Part Number: TPS79601DRBR; Vendor Part Status: Active; WEIGHT: 0.024660813g
U43 = IC_PM_LP5907-1_8_SOT23-5: IC, ANALOG, 0.25A LINEAR REGULATOR FOR RF AND ANALOG CIRCUITS-REQUIRES NO BYPASS CAPACITOR, VIN:2.2V TO 5.5V, VOUT: 1.8V, SOT23-5, SMD; ALT_SYMBOLS: SOT95P280X145-5A2L,SOT95P280X145-5A2M; Additional Datasheet URL: http://www.ti.com/litv/pdf/mpds018l; AutoDoc File: https://notefied-dynamic-precision.com/DB/Apps/Desktop/Item/Object.aspx?id=113685; BU Name: DYNAMIC PRECISION GDANSK; Budget Currency: USD; Budget Price: 0.14; Budgetary Price: 0.14 USD; Client Status: UNDER_REVIEW; Datasheet URL: http://www.ti.com/lit/ds/symlink/lp5907.pdf; Datasheet URL 1: http://www.ti.com/lit/ds/symlink/lp5907.pdf; Datasheet URL 2: N/A; Mass: 0.0181g; Max Oper Temp: +125DEGC; Maximum Operating Temperature: +125DEGC; Min Oper Temp: -40DEGC; Minimum Operating Temperature: -40DEGC; Mounting Type: SMD; NOTEfied URL: https://notefied-dynamic-precision.com/NOTEfiedWebInterface/part/show?partNumber=18-32950; PCB Package: SOT23-5; Packing Size: 3000; Packing Type: Tape & Reel; Part Number: 18-32950; Part Type: IC|ANALOG|PM|REGULATOR; ROHS: Compliant; Rated Voltage: 1.8V; Revision: R003; RoHS Status: ROHS_COMPLIANT; Rtd Voltage: 1.8V; Status: Released; Type: IC; Vendor: TEXAS INSTRUMENTS; Vendor Part Number: LP5907MFX-1.8/NOPB; Vendor Part Status: Active; Weight: 0.0181g
U44 = IC_PM_TPS73101_SOT23-5: IC, ANALOG, 0.15A LOW DROPOUT REGULATOR WITH REVERSE CURRENT PROTECTION, VIN:1.7V TO 5.5V, VOUT:1.2V TO 5.5V, SOT23-5, SMD; ALT_SYMBOLS: SOT95P280X145-5A2L,SOT95P280X145-5A2M; Additional Datasheet URL: http://www.ti.com/lit/ml/mpds018l/mpds018l.pdf; AutoDoc File: https://notefied-dynamic-precision.com/DB/Apps/Desktop/Item/Object.aspx?id=116067; BU Name: DYNAMIC PRECISION GDANSK; Budget Currency: USD; Budget Price: 0.33; Budgetary Price: 0.33 USD; Client Status: UNDER_REVIEW; Datasheet URL: http://www.ti.com/lit/ds/symlink/tps731.pdf; Datasheet URL 1: http://www.ti.com/lit/ds/symlink/tps731.pdf; Datasheet URL 2: http://www.ti.com/lit/ml/mpds018l/mpds018l.pdf; Mass: 0.0203g; Max Oper Temp: +125DEGC; Maximum Operating Temperature: +125DEGC; Min Oper Temp: -40DEGC; Minimum Operating Temperature: -40DEGC; Mounting Type: SMD; NOTEfied URL: https://notefied-dynamic-precision.com/NOTEfiedWebInterface/part/show?partNumber=18-33642; PCB Package: SOT23-5; Packing Size: 3000; Packing Type: Tape & Reel; Part Number: 18-33642; Part Type: IC|ANALOG|PM|REGULATOR; ROHS: Compliant; Rated Voltage: 1.2V TO 5.5V; Revision: R006; RoHS Status: ROHS_COMPLIANT; Rtd Voltage: 1.2V TO 5.5V; Status: Released; Texas Part Status: Under Review; Type: IC; Vendor: TEXAS INSTRUMENTS; Vendor Part Number: TPS73101DBVR; Vendor Part Status: Active; Weight: 0.0203g
FIDU1-FIDU6 = FIDMARK: NON COMPONENT, FIDUCIAL MARK, ROUND 1.27MM, SMD; Additional Datasheet URL: N/A; CLASS: IO; Country of Origin: Missing Info; Datasheet URL: N/A; Mass: N/A; Mounting Type: SMD; NOTEfied URL: https://notefied-dynamic-precision.com/NOTEfiedWebInterface/part/show?partNumber=19-00300; Packing Size: N/A; Packing Type: Missing Info; Part Number: 19-00300; ROHS: Missing Info; Revision: R006; Status: Released; Texas Part Status: Under Review; Type: Non Component; Vendor: NON_COMPONENT; Vendor Part Number: FIDUCIAL_1.27mm; Vendor Part Status: Active
LBL1 = LP_STICKER
LBL2 = TI_LOGO_V1: NON COMPONENT, LABEL, TEXAS INSTRUMENTS LOGO; Additional Datasheet URL: N/A; AutoDoc File: https://notefied-dynamic-precision.com/DB/Apps/Desktop/Item/Object.aspx?id=87770; BU Name: TEXAS INSTRUMENTS NORWAY; Country of Origin: Missing Info; Datasheet URL: N/A; Exclusive for Customers: TEXAS INSTRUMENTS NORWAY; Mass: N/A; Mounting Type: Not Apply; NOTEfied URL: https://notefied-dynamic-precision.com/NOTEfiedWebInterface/part/show?partNumber=19-00350; Notes: Custom Item; Packing Size: N/A; Packing Type: Missing Info; Part Number: 19-00350; ROHS: Missing Info; Revision: R007; Status: Released; Texas Part Status: Under Review; Type: Non Component; Vendor: NON_COMPONENT; Vendor Part Status: Active
LBL3 = CE_LABEL_V1: NON COMPONENT, LABEL, CE; Additional Datasheet URL: N/A; Country of Origin: Missing Info; Datasheet URL: http://www.ce-marking.com/CE-marking-logo.html; Mass: N/A; Mounting Type: Not Apply; NOTEfied URL: https://notefied-dynamic-precision.com/NOTEfiedWebInterface/part/show?partNumber=19-00351; Packing Size: N/A; Packing Type: Missing Info; Part Number: 19-00351; Part Type: Non Component|LABEL; ROHS: Missing Info; Revision: R009; Status: Released; Texas Part Status: Under Review; Type: Non Component; Vendor: NON_COMPONENT; Vendor Part Number: CE_LABEL; Vendor Part Status: Active
LBL4 = LABEL_FOR_EVALUATOIN_ONLY: NON COMPONENT, LABEL, FOR EVALUATION ONLY, NOT FCC APPROVED FOR RESALE; Additional Datasheet URL: N/A; AutoDoc File: https://notefied-dynamic-precision.com/DB/Apps/Desktop/Item/Object.aspx?id=115268; BU Name: TEXAS INSTRUMENTS NORWAY; Datasheet URL: N/A; Exclusive for Customers: TEXAS INSTRUMENTS NORWAY; Maximum Operating Temperature: N/A; Minimum Operating Temperature: N/A; Mounting Type: Not Apply; NOTEfied URL: https://notefied-dynamic-precision.com/NOTEfiedWebInterface/part/show?partNumber=19-00830; Notes: Custom Item; Part Number: 19-00830; REACH/SVHC Compliance: Missing Info; REACH/SVHC Details: N/A; REACH/SVHC Source: N/A; REACH/SVHC Status: Missing Info; ROHS: Missing Info; Revision: R007; Status: Released; Texas Part Status: Under Review; Type: Non Component; Vendor: NON_COMPONENT; Vendor Part Status: Active
LBL5 = TRASH_V2: NON COMPONENT, LABEL, TRASH 7mm; Additional Datasheet URL: N/A; Country of Origin: Missing Info; Datasheet URL: N/A; Mass: N/A; Mounting Type: Not Apply; NOTEfied URL: https://notefied-dynamic-precision.com/NOTEfiedWebInterface/part/show?partNumber=19-01044; Packing Size: N/A; Packing Type: Missing Info; Part Number: 19-01044; Part Type: Non Component|LABEL; ROHS: Missing Info; Revision: R002; Status: Released; Texas Part Status: Under Review; Type: Non Component; Vendor: NON_COMPONENT; Vendor Part Status: Active
LBL6 = ESD_LABEL: NON COMPONENT, LABEL, ESD, 5 X 5 mm; Additional Datasheet URL: N/A; Country of Origin: Missing Info; Datasheet URL: N/A; Mass: N/A; Maximum Operating Temperature: N/A; Minimum Operating Temperature: N/A; Mounting Type: Not Apply; NOTEfied URL: https://notefied-dynamic-precision.com/NOTEfiedWebInterface/part/show?partNumber=19-00471; Packing Size: N/A; Packing Type: Missing Info; Part Number: 19-00471; Part Type: Non Component|LABEL; ROHS: Not Applicable; Revision: R004; Status: Released; Type: Non Component; Vendor: NON_COMPONENT; Vendor Part Status: Active
LBL7 = LABEL_UKCA: NON COMPONENT, LABEL, UKCA, 6 X 6mm; Additional Datasheet URL: N/A; Country of Origin: Missing Info; Datasheet URL: N/A; Maximum Operating Temperature: N/A; Minimum Operating Temperature: N/A; Mounting Type: NOT APPLY; NOTEfied URL: https://notefied-dynamic-precision.com/NOTEfiedWebInterface/part/show?partNumber=19-01541; Part Number: 19-01541; Part Type: Non Component|LABEL; REACH/SVHC Details: SVHC List Version; ROHS: Not Applicable; Revision: R002; Status: Released; Texas Part Status: Under Review; Type: Non Component; Vendor: NON_COMPONENT; Vendor Part Status: Active
M1 = MECH_SHUNT_JUMPER_V1: MECHANIC, SHUNT, CURRENT RATING 4.3A PER PIN, 2.54 X 5.08 X 6.1mm, BLACK; Additional Datasheet URL: http://suddendocs.samtec.com/prints/snt-100-xx-x-x-mkt.pdf; AutoDoc File: https://notefied-dynamic-precision.com/DB/Apps/Desktop/Item/Object.aspx?id=104092; BU Name: DYNAMIC PRECISION GDANSK; Budget Currency: USD; Budget Price: 0.146; Budgetary Price: 0.146 USD; Client Status: UNDER_REVIEW; Country of Origin: China,Costa Rica,Malaysia,Singapore,United States; Datasheet URL: http://suddendocs.samtec.com/catalog_english/snt.pdf; Datasheet URL 1: http://suddendocs.samtec.com/catalog_english/snt.pdf; Datasheet URL 2: http://suddendocs.samtec.com/prints/snt-100-xx-x-x-mkt.pdf; Lead Time: 1; Mass: 0.11724g; Max Oper Temp: +125DEGC; Maximum Operating Temperature: +125DEGC; Min Oper Temp: -55DEGC; Minimum Operating Temperature: -55DEGC; Mounting Type: Not Apply; NOTEfied URL: https://notefied-dynamic-precision.com/NOTEfiedWebInterface/part/show?partNumber=19-00498; Packing Size: 1; Packing Type: Bulk; Part Number: 19-00498; Part Type: Mechanic|SHUNT; REACH/SVHC Compliance: Compliant; REACH/SVHC Details: SVHC List Version Dec 17, 2015; REACH/SVHC Source: Material Declaration; REACH/SVHC Status: Unaffected; REACH/SVHC_COMPLIANCE: COMPLIANT; REACH/SVHC_DETAILS: SVHC LIST VERSION Dec 17, 2015; REACH/SVHC_SOURCE: MATERIAL DECLARATION; REACH/SVHC_STATUS: UNAFFECTED; ROHS: Compliant; Rated Current: 4.3A; Revision: R007; RoHS Status: ROHS_COMPLIANT; Rtd Current: 4.3A; Status: Released; Texas Part Status: Under Review; Type: Mechanic; Vendor: SAMTEC; Vendor Part Status: Active; Weight: 0.11724g
M15-M18 = MECH_SPACERS_SUPPORT_V1: MECHANIC, ACCESSORY, SPACER SUPPORT, PCB DIA. 3mm, NYLON 66, PTH; Additional Datasheet URL: N/A; Datasheet URL: N/A; Maximum Operating Temperature: N/A; Minimum Operating Temperature: N/A; Mounting Type: PTH; NOTEfied URL: https://notefied-dynamic-precision.com/NOTEfiedWebInterface/part/show?partNumber=13-04664; Part Number: 13-04664; Part Type: Mechanic|ACCESSORY; REACH/SVHC Compliance: Compliant; REACH/SVHC Details: SVHC List Version Jul 7, 2017; REACH/SVHC Source: REACH Declaration; REACH/SVHC Status: Unaffected; ROHS: Compliant; Revision: R002; Status: Released; Texas Part Status: Under Review; Type: Mechanic; Vendor: SUZHOU SOLY ELECTRICIAN; Vendor Part Status: Active
MH1-MH4 = HOLE_PTH: NON COMPONENT, HOLE 3.2mm, PLATED HOLE, PTH; Additional Datasheet URL: N/A; Country of Origin: Missing Info; Datasheet URL: N/A; Mass: N/A; Mounting Type: PTH; NOTEfied URL: https://notefied-dynamic-precision.com/NOTEfiedWebInterface/part/show?partNumber=19-00083; Packing Size: N/A; Packing Type: Missing Info; Part Number: 19-00083; Part Type: Non Component|HOLE|PLATED; ROHS: Missing Info; Revision: R006; Status: Released; Type: Non Component; Vendor: NON_COMPONENT; Vendor Part Number: HOLE_3.2mm_PLATED; Vendor Part Status: Active
MH5 = HOLE_PTH: NON COMPONENT, HOLE 1.1mm, PLATED HOLE, PTH; Additional Datasheet URL: N/A; AutoDoc File: http://notefied-dynamic-precision.com/DB/Apps/Desktop/Item/Object.aspx?id=57341; Country of Origin: Missing Info; Datasheet URL: N/A; FPLIST: MTG110_170,; Mass: N/A; Mounting Type: PTH; NOTEfied URL: https://notefied-dynamic-precision.com/NOTEfiedWebInterface/part/show?partNumber=19-00062; Packing Size: N/A; Packing Type: Missing Info; Part Number: 19-00062; ROHS: Missing Info; Revision: R003; Status: Released; Type: Non Component; Vendor: NON_COMPONENT; Vendor Part Number: HOLE_1.1mm_PLATED; Vendor Part Status: Active
PCB1 = PCB_V2: NON COMPONENT, PCB, TEXAS INSTRUMENTS; Additional Datasheet URL: N/A; Datasheet URL: N/A; Exclusive for Customers: TEXAS INSTRUMENTS NORWAY; Mounting Type: Not Apply; NOTEfied URL: https://notefied-dynamic-precision.com/NOTEfiedWebInterface/part/show?partNumber=19-00925; Notes: Custom PCB outline.; Packing Type: Missing Info; Part Number: 19-00925; Part Type: Non Component|PCB; ROHS: Missing Info; Revision: R003; Status: Released; Texas Part Status: Under Review; Type: Non Component; Vendor: TEXAS INSTRUMENTS; Vendor Part Number: PCB; Vendor Part Status: Active

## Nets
5V0: C151.1 C152.1 C157.1 C160.1 C161.1 C164.1 C168.1 C484.1 FL5.2 R354.2 U42.1(IN) U42.2(IN) U42.8(EN) U43.1(IN) U43.3(EN) U44.1(IN) U44.3(EN) ; also on sheet 1 2
GND: C151.2 C152.2 C154.2 C155.2 C156.2 C157.2 C158.2 C159.2 C160.2 C161.2 C162.2 C163.2 C164.2 C165.2 C166.2 C168.2 C171.2 C174.2 C175.2 C484.2 C485.2 C486.2 MH1.1 MH2.1 MH3.1 MH4.1 MH5.1 R133.1 R135.1 R152.1 U42.6(GND) U42.9(GND/TAB) U43.2(GND) U44.2(GND) U46.6(GND) U46.9(GND/TAB) ; also on sheet 1 2 3
ET_1V8: C158.1 C159.1 U43.5(OUT) ; also on sheet 3
ET_3V3: C153.1 C154.1 C155.1 C156.1 R132.2 U42.3(OUT) U42.4(OUT) ; also on sheet 3
ET_5V0: C165.1 FL4.1 ; also on sheet 3
ET_VDD: C172.1 C174.1 C485.1 C486.1 R151.2 U46.3(OUT) U46.4(OUT) ; also on sheet 1
SW_VDD: C162.1 C163.1 R134.2 U44.5(OUT) ; also on sheet 3
N2992079: C171.1 C175.1 FL5.1 U46.1(IN) U46.2(IN) U46.8(EN)
N2992279: C153.2 R132.1 R133.2 U42.5(FB)
N2992427: C172.2 R151.1 R152.2 U46.5(FB)
N2992751: C166.1 FL4.2 R354.1
N2993203: R134.1 R135.2 U44.4(NR/FB)

Not connected (* = marked no-connect by the designer): FIDU1 1*; FIDU2 1*; FIDU3 1*; FIDU4 1*; FIDU5 1*; FIDU6 1*; U42 7(NC)*; U43 4(NC)*; U46 7(NC)*

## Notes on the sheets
sheet 4
- EnergyTrace Power Supply
- U24 VCC set at 3.6V, higher than
  switch supplies to prevent current
  through protection diodes
sheet 5
- Mechanical
- Jumpers
- P9:
- Mount on Pin 1-2
- PCB
- Labels
- Mounting Holes
- Stickers
- Fiducials
- Place sticker on bottom side.
